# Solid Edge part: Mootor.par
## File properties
Author: Egon 815
Template: Normal.par
Last saved by: Egon 815
Revision: 16
Application: Solid Edge
Accuracy: 0,990
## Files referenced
..\Laev.asm
.C:\Kool\3D Modelleerimine\LaevaJoonis\Laev.asm
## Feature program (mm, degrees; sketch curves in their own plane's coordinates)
sketch for "v_2" #1 plane through (0, 66095.292, 0) normal (0, -1, 0) x-axis (1, 0, 0)
sketch for "v_2" #2 plane through (0, 66095.292, 0) normal (0, -1, 0) x-axis (1, 0, 0)
  circle centre (6000, -3000) radius 1000
extrude "v_2" add finite 8000 along -normal
sketch for "v_1" plane through (0, 66095.292, 0) normal (0, -1, 0) x-axis (1, 0, 0)
extrude "v_1" add finite 8000 along -normal
sketch used by "ExtrudedProtrusion_4" plane through (0, 74095.292, 0) normal (0, -1, 0) x-axis (1, 0, 0)
  circle centre (0, 0) radius 400
  line (0, 0) -> (0, 0)
extrude "ExtrudedProtrusion_4" add finite 7000 along -normal
sketch for "ExtrudedProtrusion_5" plane through (0, 74095.292, 0) normal (0, -1, 0) x-axis (1, 0, 0)
extrude "ExtrudedProtrusion_5" add finite 8000 along -normal
sketch for "ExtrudedCutout_1" plane through (6000, 81095.292, -3000) normal (0, 1, 0) x-axis (-1, 0, 0)
  circle centre (0, 0) radius 400
extrude "ExtrudedCutout_1" cut finite 500 along -normal
sketch for "ExtrudedCutout_2" plane through (0, 82095.292, -4045.3629) normal (0, 1, 0) x-axis (-1, 0, 0)
extrude "ExtrudedCutout_2" cut finite 500 along -normal
sketch for "ExtrudedCutout_3" plane through (-6000, 81095.292, -3000) normal (0, 1, 0) x-axis (-1, 0, 0)
  circle centre (0, 0) radius 400
extrude "ExtrudedCutout_3" cut finite 500 along -normal
fillet "Round_2" radius 200
chamfer "Chamfer_1" setback 250
sketch used by "ExtrudedProtrusion_6" plane through (0, 0, 0) normal (1, 0, 0) x-axis (0, 1, 0)
  line (86724.9498, -1943.6839) -> (86724.9498, -6077.5909)
  line (87724.9498, -7077.5909) -> (98627.3057, -7077.5909)
  line (99627.3057, -6077.5909) -> (99627.3057, -1943.6839)
  line (98627.3057, -943.6839) -> (87724.9498, -943.6839)
  arc centre (87724.9498, -1943.6839) radius 1000 from (86724.9498, -1943.6839) to (87724.9498, -943.6839) cw
  arc centre (87724.9498, -6077.5909) radius 1000 from (86724.9498, -6077.5909) to (87724.9498, -7077.5909) ccw
  arc centre (98627.3057, -1943.6839) radius 1000 from (99627.3057, -1943.6839) to (98627.3057, -943.6839) ccw
  arc centre (98627.3057, -6077.5909) radius 1000 from (98627.3057, -7077.5909) to (99627.3057, -6077.5909) ccw
  line (87724.9498, -943.6839) -> (87724.9498, 2056.3161)
  line (87724.9498, 2056.3161) -> (89724.9498, 2056.3161)
  line (89724.9498, 2056.3161) -> (89724.9498, -943.6839)
extrude "ExtrudedProtrusion_6" add finite 100 symmetric
chamfer "Chamfer_2" setback 50
sketch used by "unnamed Protrusion 1" plane through (0, 0, 1000) normal (0, 0, 1) x-axis (1, 0, 0)
extrude "unnamed Protrusion 1" add to key point along -normal
chamfer "Chamfer_5" setback 1000
fillet "Round_3" radius 300
sketch for "ExtrudedProtrusion_9" plane through (0, 61095.292, 0) normal (0, -1, 0) x-axis (1, 0, 0)
  arc centre (-15020.7073, 1014.2236) radius 25000 from (9742.9982, 4443.3471) to (9742.9982, -2414.8998) cw
  arc centre (0, 6627.4675) radius 13292.4949 from (-9742.9982, -2414.8998) to (9742.9982, -2414.8998) ccw
  arc centre (15020.7073, 1014.2236) radius 25000 from (-9742.9982, 4443.3471) to (-9742.9982, -2414.8998) ccw
  line (-9742.9982, 4443.3471) -> (9742.9982, 4443.3471)
extrude "ExtrudedProtrusion_9" add finite 20000 along +normal
lofted protrusion "unnamed LoftedProtrusion 1"
lofted protrusion "unnamed LoftedProtrusion 2"
lofted protrusion "unnamed LoftedProtrusion 3"
sketch for "ExtrudedProtrusion_10" plane through (0, 88724.9498, 1000) normal (0, 0, 1) x-axis (1, 0, 0)
  line (1250, 1226.4456) -> (-1250, 1226.4456)
  line (-1250, 1226.4456) -> (-1250, -1273.5544)
  line (-1250, -1273.5544) -> (1250, -1273.5544)
  line (1250, -1273.5544) -> (1250, 1226.4456)
extrude "ExtrudedProtrusion_10" add finite 2500 along +normal
lofted protrusion "unnamed LoftedProtrusion 4"
lofted protrusion "unnamed LoftedProtrusion 5"
fillet "Round_4" radius 500
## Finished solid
Body 1: solid body, 94 faces, 207 edges, 117 vertices.
  Faces by surface: plane 27, cylinder 26, spline 15, blend 9, cone 7, torus 6, sphere 4
  Edges by curve: circle 66, line 63, intersection 47, ellipse 12, spline 12, curve on surface 7
Bounding box of the edges (mm; curved faces can reach further): 19958.585 x 58532.014 x 11520.938, from (-9979.2927, 41095.292, -7077.5909) to (9979.2927, 99627.3057, 4443.3471).
Cylindrical faces by radius (mm): R400 x3, R500 x11, R750 x3, R1000 x6, R13292.4949 x1, R25000 x2
Conical faces (half-angle, radius in mm at the cone's reference point): 45 deg R750 x2, 45 deg R950 x2, 45 deg R1000 x3
Toroidal faces (ring radius, tube radius in mm): R550 r200 x3, R600 r200 x3
Spherical faces by radius (mm): R500 x4
Planar faces by outward normal: +x 2, +y 6, +z 2, -x 2, -y 1, -z 3, oblique 11
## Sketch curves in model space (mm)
line (1250, 66095.292, 3500) -> (1250, 66095.292, 1000)
line (-1250, 66095.292, 3500) -> (1250, 66095.292, 3500)
line (-1250, 66095.292, 3500) -> (-1250, 66095.292, 1000)
line (-1250, 66095.292, 1000) -> (1250, 66095.292, 1000)
circle centre (6000, 81095.292, -3000) radius 400
circle centre (-6000, 81095.292, -3000) radius 400
circle centre (0, 88724.9498, 1000) radius 1000
circle centre (6000, 74095.292, -3000) radius 750
circle centre (0, 74095.292, -4045.3629) radius 750
circle centre (-6000, 74095.292, -3000) radius 750
circle centre (0, 82095.292, -4045.3629) radius 400
arc centre (-15020.7073, 61095.292, 1014.2236) radius 25000 from (9742.9982, 61095.292, 4443.3471) through (9979.2927, 61095.292, 1014.2236) to (9742.9982, 61095.292, -2414.8998)
arc centre (0, 61095.292, 6627.4675) radius 13292.4949 from (-9742.9982, 61095.292, -2414.8998) through (0, 61095.292, -6665.0274) to (9742.9982, 61095.292, -2414.8998)
arc centre (15020.7073, 61095.292, 1014.2236) radius 25000 from (-9742.9982, 61095.292, 4443.3471) through (-9979.2927, 61095.292, 1014.2236) to (-9742.9982, 61095.292, -2414.8998)
line (-9742.9982, 61095.292, 4443.3471) -> (9742.9982, 61095.292, 4443.3471)
line (0, 98627.3057, -943.6839) -> (0, 87724.9498, -943.6839)
arc centre (0, 98627.3057, -1943.6839) radius 1000 from (0, 99627.3057, -1943.6839) through (0, 99313.5474, -1216.3103) to (0, 98627.3057, -943.6839)
line (0, 99627.3057, -6077.5909) -> (0, 99627.3057, -1943.6839)
arc centre (0, 98627.3057, -6077.5909) radius 1000 from (0, 98627.3057, -7077.5909) through (0, 99354.6794, -6763.8325) to (0, 99627.3057, -6077.5909)
line (0, 87724.9498, -7077.5909) -> (0, 98627.3057, -7077.5909)
arc centre (0, 87724.9498, -6077.5909) radius 1000 from (0, 86724.9498, -6077.5909) through (0, 87038.7082, -6804.9645) to (0, 87724.9498, -7077.5909)
arc centre (0, 87724.9498, -1943.6839) radius 1000 from (0, 86724.9498, -1943.6839) through (0, 87038.7082, -1216.3103) to (0, 87724.9498, -943.6839)
line (0, 86724.9498, -1943.6839) -> (0, 86724.9498, -6077.5909)
line (0, 89724.9498, 2056.3161) -> (0, 89724.9498, -943.6839)
line (0, 87724.9498, 2056.3161) -> (0, 89724.9498, 2056.3161)
line (0, 87724.9498, -943.6839) -> (0, 87724.9498, 2056.3161)
circle centre (6000, 66095.292, -3000) radius 1000
circle centre (0, 66095.292, -4000) radius 1000
circle centre (-6000, 66095.292, -3000) radius 1000
circle centre (0, 66095.292, -4000) radius 1000
arc centre (4185.1243, 66095.292, -12615.4047) radius 5926.2428 from (4371.7702, 66095.292, -6692.1018) through (2007.2841, 66095.292, -7103.8382) to (0, 66095.292, -8419.563)
arc centre (-4185.1243, 66095.292, -12615.4047) radius 5926.2428 from (-4371.7702, 66095.292, -6692.1018) through (-2007.2841, 66095.292, -7103.8382) to (0, 66095.292, -8419.563)
arc centre (-6098.5646, 66095.292, -470.8784) radius 6456.4262 from (-9744.6378, 66095.292, -5799.2543) through (-7156.9605, 66095.292, -6839.9629) to (-4371.7702, 66095.292, -6692.1018)
arc centre (-1803.2627, 66095.292, -494.6187) radius 9550.1099 from (-11353.3694, 66095.292, -486.8867) through (-10943.4649, 66095.292, -3262.5242) to (-9744.6378, 66095.292, -5799.2543)
arc centre (-72636.1359, 66095.292, 2896.0245) radius 61376.0666 from (-11499.3187, 66095.292, 8310) through (-11268.5148, 66095.292, 3914.1752) to (-11353.3694, 66095.292, -486.8867)
line (-11499.3187, 66095.292, 8310) -> (11499.3187, 66095.292, 8310)
arc centre (72636.1359, 66095.292, 2896.0245) radius 61376.0666 from (11499.3187, 66095.292, 8310) through (11268.5148, 66095.292, 3914.1752) to (11353.3694, 66095.292, -486.8867)
arc centre (1803.2627, 66095.292, -494.6187) radius 9550.1099 from (11353.3694, 66095.292, -486.8867) through (10943.4649, 66095.292, -3262.5242) to (9744.6378, 66095.292, -5799.2543)
arc centre (6098.5646, 66095.292, -470.8784) radius 6456.4262 from (9744.6378, 66095.292, -5799.2543) through (7156.9605, 66095.292, -6839.9629) to (4371.7702, 66095.292, -6692.1018)
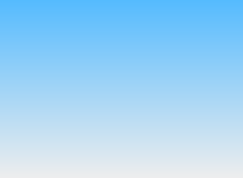
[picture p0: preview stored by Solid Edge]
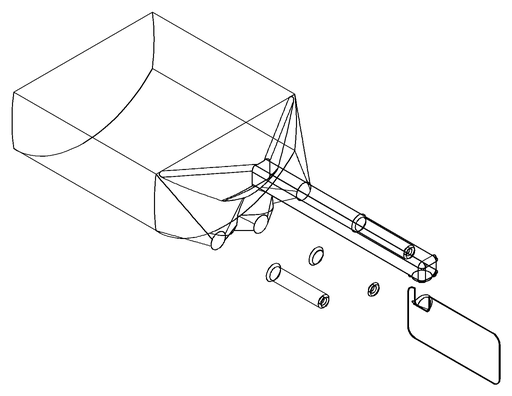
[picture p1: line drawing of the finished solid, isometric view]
